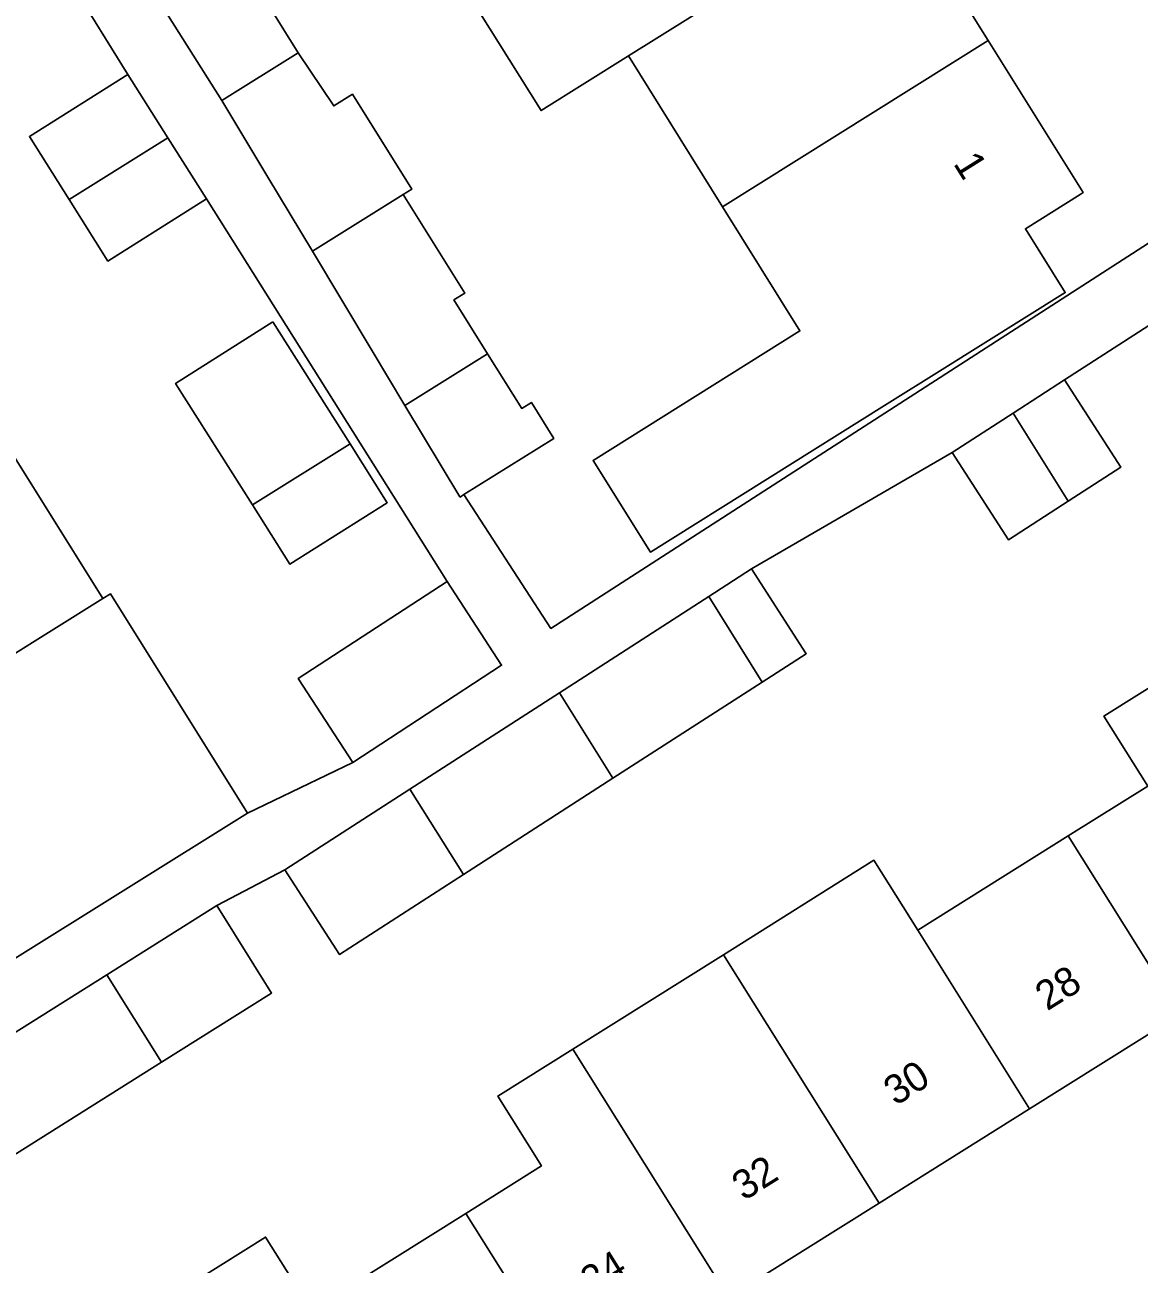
# Model space of a CAD drawing. Extents: x 159352 to 160617, y 385888 to 387323.
# Drawn here: x 159789.16 to 159827.49, y 386145.65 to 386188.27 of the extents above; entities that cross this region are included whole.
import ezdxf

# ---------------------------------------------------------------- set-up
doc = ezdxf.new("R2010")
doc.units = 0
for name, color, linetype in [('IMGEO_Erf', 7, 'Continuous'), ('IMGEO_Pand', 7, 'Continuous'), ('IMGEO_Pand_nummerreeks', 7, 'Continuous'), ('IMGEO_Voetpad_open', 7, 'Continuous')]:
    doc.layers.add(name, color=color, linetype=linetype)

msp = doc.modelspace()

# ---------------------------------------------------------------- linework, layer by layer
at = {"layer": 'IMGEO_Erf'}
for points in [[(159788.288, 386197.868), (159790.961, 386199.537), (159792.117, 386197.686), (159792.463, 386197.899), (159793.635, 386196.021), (159795.646, 386192.8), (159795.293, 386192.579), (159798.563, 386187.303), (159799.788, 386185.479), (159800.433, 386185.882), (159802.473, 386182.616), (159802.182, 386182.435), (159804.3, 386179.044), (159803.925, 386178.81), (159805.08, 386176.96), (159806.255, 386175.079), (159806.587, 386175.286), (159807.36, 386174.049), (159804.267, 386172.115), (159807.258, 386167.515), (159831.974, 386183.449), (159795.649, 386239.796), (159793.173, 386240.363), (159775.161, 386229.041)], [(159819.062, 386192.912), (159822.303, 386187.731), (159825.572, 386182.504), (159825.46, 386182.434), (159823.578, 386181.257), (159824.951, 386179.062), (159820.712, 386176.411), (159818.733, 386175.173), (159810.683, 386170.138), (159808.711, 386173.292), (159815.824, 386177.741), (159813.16, 386182.013), (159809.925, 386187.199), (159806.922, 386185.321), (159803.682, 386190.503)], [(159788.609, 386173.739), (159791.851, 386168.545), (159792.11, 386168.707), (159796.821, 386161.165), (159800.45, 386162.907), (159798.571, 386165.786), (159803.686, 386169.124), (159795.41, 386182.281), (159792.021, 386180.145), (159790.688, 386182.26), (159789.322, 386184.429), (159792.71, 386186.564), (159788.923, 386192.666)], [(159799.155, 386144.152), (159804.336, 386147.398), (159806.935, 386149.026), (159805.429, 386151.428), (159808.01, 386153.046), (159813.191, 386156.293), (159818.369, 386159.538), (159819.876, 386157.133), (159825.056, 386160.379), (159827.788, 386162.09), (159826.281, 386164.497), (159828.729, 386166.03), (159831.275, 386167.625), (159832.783, 386165.219), (159835.545, 386166.949), (159839.394, 386160.805), (159834.087, 386157.48), (159828.906, 386154.235), (159823.726, 386150.99), (159818.546, 386147.745), (159813.366, 386144.5)], [(159795.134, 386145.132), (159797.447, 386146.58), (159799.02, 386144.068)]]:
    msp.add_lwpolyline(points, dxfattribs=at)
for points in [[(159833.271, 386181.437), (159824.924, 386176.057), (159826.859, 386173.057), (159825.055, 386171.893), (159822.993, 386170.563), (159821.058, 386173.563), (159814.163, 386169.557), (159816.04, 386166.644), (159814.526, 386165.669), (159809.39, 386162.36), (159804.249, 386159.047), (159799.984, 386156.3), (159798.107, 386159.213), (159795.764, 386157.98), (159797.654, 386154.974), (159793.866, 386152.593), (159786.792, 386148.147), (159784.903, 386151.153), (159782.471, 386149.624), (159797.259, 386126.043), (159846.619, 386157.053), (159847.175, 386159.869)], [(159797.698, 386178.056), (159800.351, 386173.859), (159801.629, 386171.836), (159798.281, 386169.72), (159796.992, 386171.759), (159794.35, 386175.94)]]:
    msp.add_lwpolyline(points, close=True, dxfattribs=at)
at = {"layer": 'IMGEO_Pand'}
for points in [[(159819.062, 386192.912), (159815.821, 386198.094), (159806.691, 386192.385), (159803.682, 386190.503), (159806.922, 386185.321), (159809.925, 386187.199)], [(159822.303, 386187.731), (159819.062, 386192.912), (159809.925, 386187.199), (159813.16, 386182.013)], [(159795.293, 386192.579), (159792.629, 386190.916), (159795.941, 386185.664), (159798.563, 386187.303)], [(159813.16, 386182.013), (159815.824, 386177.741), (159808.711, 386173.292), (159810.683, 386170.138), (159818.733, 386175.173), (159820.712, 386176.411), (159824.951, 386179.062), (159823.578, 386181.257), (159825.46, 386182.434), (159825.572, 386182.504), (159822.303, 386187.731)], [(159798.563, 386187.303), (159795.941, 386185.664), (159797.526, 386183.027), (159799.056, 386180.482), (159802.182, 386182.435), (159802.473, 386182.616), (159800.433, 386185.882), (159799.788, 386185.479)], [(159792.71, 386186.564), (159789.322, 386184.429), (159790.688, 386182.26), (159794.085, 386184.384)], [(159792.021, 386180.145), (159795.41, 386182.281), (159794.085, 386184.384), (159790.688, 386182.26)], [(159802.182, 386182.435), (159799.056, 386180.482), (159801.116, 386177.055), (159802.24, 386175.184), (159805.08, 386176.96), (159803.925, 386178.81), (159804.3, 386179.044)], [(159797.698, 386178.056), (159794.35, 386175.94), (159796.992, 386171.759), (159800.351, 386173.859)], [(159805.08, 386176.96), (159802.24, 386175.184), (159804.13, 386172.041), (159804.135, 386172.032), (159804.267, 386172.115), (159807.36, 386174.049), (159806.587, 386175.286), (159806.255, 386175.079)], [(159825.055, 386171.893), (159826.859, 386173.057), (159824.924, 386176.057), (159823.159, 386174.919)], [(159823.159, 386174.919), (159821.058, 386173.563), (159822.993, 386170.563), (159825.055, 386171.893)], [(159791.851, 386168.545), (159788.609, 386173.739), (159780.167, 386168.46), (159783.411, 386163.268)], [(159798.281, 386169.72), (159801.629, 386171.836), (159800.351, 386173.859), (159796.992, 386171.759)], [(159812.686, 386168.606), (159814.526, 386165.669), (159816.04, 386166.644), (159814.163, 386169.557)], [(159800.45, 386162.907), (159805.564, 386166.245), (159803.686, 386169.124), (159798.571, 386165.786)], [(159787.012, 386158.446), (159788.543, 386155.995), (159796.821, 386161.165), (159792.11, 386168.707), (159791.851, 386168.545), (159783.411, 386163.268), (159784.708, 386161.192), (159783.978, 386160.736), (159785.544, 386158.248), (159786.265, 386158.698), (159786.588, 386158.181)], [(159814.526, 386165.669), (159812.686, 386168.606), (159807.55, 386165.297), (159809.39, 386162.36)], [(159825.056, 386160.379), (159828.906, 386154.235), (159834.087, 386157.48), (159830.237, 386163.624), (159828.729, 386166.03), (159826.281, 386164.497), (159827.788, 386162.09)], [(159809.39, 386162.36), (159807.55, 386165.297), (159802.408, 386161.984), (159804.249, 386159.047)], [(159804.249, 386159.047), (159802.408, 386161.984), (159798.107, 386159.213), (159799.984, 386156.3)], [(159825.056, 386160.379), (159819.876, 386157.133), (159823.726, 386150.99), (159828.906, 386154.235)], [(159814.697, 386153.889), (159818.546, 386147.745), (159823.726, 386150.99), (159819.876, 386157.133), (159818.369, 386159.538), (159813.191, 386156.293)], [(159793.866, 386152.593), (159797.654, 386154.974), (159795.764, 386157.98), (159791.981, 386155.602)], [(159813.191, 386156.293), (159808.01, 386153.046), (159809.516, 386150.643), (159813.366, 386144.5), (159818.546, 386147.745), (159814.697, 386153.889)], [(159791.981, 386155.602), (159784.903, 386151.153), (159786.792, 386148.147), (159793.866, 386152.593)], [(159804.336, 386147.398), (159808.184, 386141.254), (159813.366, 386144.5), (159809.516, 386150.643), (159808.01, 386153.046), (159805.429, 386151.428), (159806.935, 386149.026)], [(159803.004, 386138.009), (159808.184, 386141.254), (159804.336, 386147.398), (159799.155, 386144.152)], [(159799.155, 386144.152), (159799.02, 386144.068), (159797.447, 386146.58), (159795.134, 386145.132), (159790.896, 386142.477), (159791.884, 386140.9), (159790.22, 386139.858), (159793.319, 386134.911), (159796.362, 386136.818), (159797.698, 386134.685), (159803.004, 386138.009)]]:
    msp.add_lwpolyline(points, close=True, dxfattribs=at)
at = {"layer": 'IMGEO_Voetpad_open'}
for points in [[(159788.923, 386192.666), (159792.71, 386186.564), (159794.085, 386184.384), (159795.41, 386182.281), (159803.686, 386169.124), (159805.564, 386166.245), (159800.45, 386162.907), (159796.821, 386161.165), (159788.543, 386155.995)], [(159784.903, 386151.153), (159791.981, 386155.602), (159795.764, 386157.98), (159798.107, 386159.213), (159802.408, 386161.984), (159807.55, 386165.297), (159812.686, 386168.606), (159814.163, 386169.557), (159821.058, 386173.563), (159823.159, 386174.919), (159824.924, 386176.057), (159833.271, 386181.437), (159831.974, 386183.449), (159807.258, 386167.515), (159804.267, 386172.115), (159804.135, 386172.032), (159804.13, 386172.041), (159802.24, 386175.184), (159801.116, 386177.055), (159799.056, 386180.482), (159797.526, 386183.027), (159795.941, 386185.664), (159792.629, 386190.916)]]:
    msp.add_lwpolyline(points, dxfattribs=at)

# ---------------------------------------------------------------- texts
at = {"layer": 'IMGEO_Pand_nummerreeks'}
for s, rotation, p in [('1', 302.0233, (159821.079, 386183.502)), ('28', 32.0646, (159824.328, 386154.341)), ('30', 32.0646, (159819.116, 386151.076)), ('32', 32.0646, (159813.899, 386147.808)), ('34', 32.0646, (159808.69, 386144.545))]:
    msp.add_text(s, height=1, rotation=rotation, dxfattribs=at).set_placement(p)

doc.saveas('drawing.dxf')
